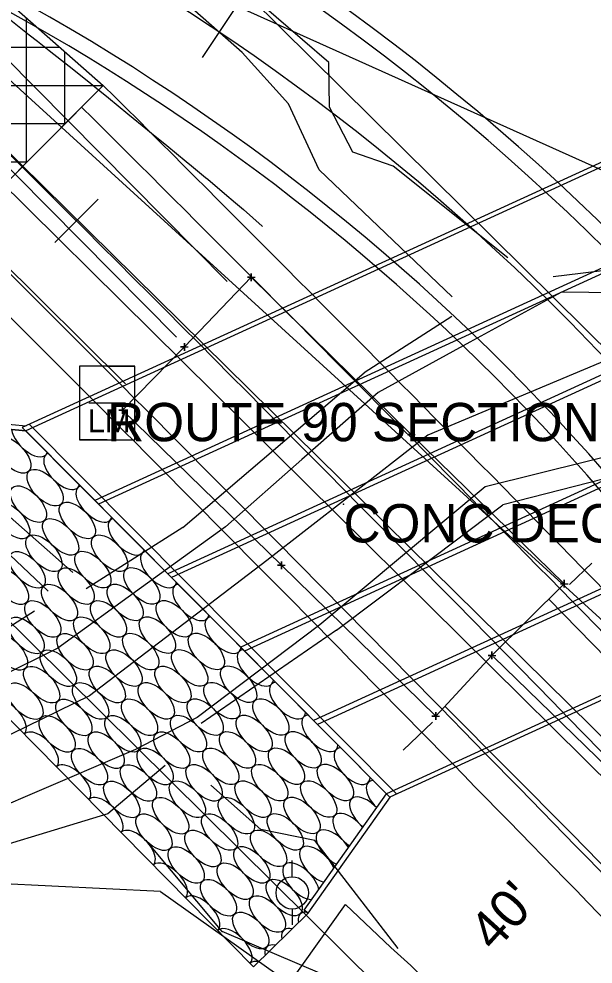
# Model space of a CAD drawing. Extents: x 1660112 to 1662239, y 668919 to 671377.
# Drawn here: x 1661235.6 to 1661310.6, y 670188.6 to 670311.9 of the extents above; entities that cross this region are included whole.
import ezdxf

# ---------------------------------------------------------------- set-up
doc = ezdxf.new("R2010")
doc.units = 0
for name, color, linetype in [('R_Axis', 7, 'Continuous'), ('R_Concrete', 7, 'Continuous'), ('R_Concrete Hidden', 7, 'Continuous'), ('R_Horz Alg', 7, 'Continuous'), ('R_Horz Alg Annot', 7, 'Continuous'), ('R_Proposed Const Limits_Cut', 7, 'Continuous'), ('R_Proposed Const Limits_Fill', 7, 'Continuous'), ('R_Proposed Const Limits_Hand', 7, 'Continuous'), ('R_Proposed Road_Lane', 7, 'Continuous'), ('R_Proposed Road_Shoulder', 7, 'Continuous'), ('R_Water Annot', 7, 'Continuous'), ('S_BASELINE', 7, 'Continuous'), ('S_BRIDGE', 7, 'Continuous'), ('S_DITCHLINE', 7, 'Continuous'), ('S_EDGE_PAVEMENT', 7, 'Continuous'), ('S_EXIST_ROW', 7, 'Continuous'), ('S_EXIST_ROW_ANNOT', 7, 'Continuous'), ('S_EXISTING_ALIGNMENT', 7, 'Continuous'), ('S_LOG_MILE', 7, 'Continuous'), ('S_LOG_MILE_ANNOT', 7, 'Continuous'), ('S_MSC_PT_SYM', 7, 'Continuous'), ('S_PAVEMENT_CROWN', 7, 'Continuous'), ('S_STR_PT_SYM', 7, 'Continuous'), ('S_STREAM', 7, 'Continuous'), ('S_SURVEY_TEXT_ANNOT', 7, 'Continuous'), ('S_UTILITY_POLE', 7, 'Continuous'), ('S_UTL_PT_SYM', 7, 'Continuous'), ('S_WALL', 7, 'Continuous'), ('S_WATER_UTILITIES', 7, 'Continuous')]:
    doc.layers.add(name, color=color, linetype=linetype)

msp = doc.modelspace()

# ---------------------------------------------------------------- linework, layer by layer
at = {"layer": 'R_Axis'}
for p, q in [((1661236.63, 670293.2), (1661236.63, 670312.05)), ((1661201.2, 670308.25), (1661240.96, 670308.25)), ((1661241.63, 670298.22), (1661241.63, 670307.65)), ((1661205.82, 670303.25), (1661246.63, 670303.25)), ((1661210.44, 670298.25), (1661241.66, 670298.25)), ((1661215.06, 670293.25), (1661236.68, 670293.25))]:
    msp.add_line(p, q, dxfattribs=at)
msp.add_lwpolyline([(1661157.58, 670355.45), (1661171.41, 670369.49), (1661246.63, 670303.25), (1661225.47, 670281.99)], close=True, dxfattribs=at)
at = {"layer": 'R_Concrete'}
for p, q in [((1661313.49, 670294.08), (1661236.07, 670258.59)), ((1661313.49, 670294.08), (1661236.07, 670258.59)), ((1661208.1, 670261.48), (1661236.56, 670258.81)), ((1661208.1, 670261.48), (1661236.56, 670258.81)), ((1661208.04, 670260.82), (1661236.51, 670258.15)), ((1661208.04, 670260.82), (1661236.51, 670258.15)), ((1661236.99, 670259.01), (1661284.96, 670210.78)), ((1661236.99, 670259.01), (1661284.96, 670210.78)), ((1661236.07, 670258.59), (1661284.05, 670210.36)), ((1661236.07, 670258.59), (1661284.05, 670210.36)), ((1661361.21, 670245.74), (1661284.05, 670210.36)), ((1661361.21, 670245.74), (1661284.05, 670210.36)), ((1661272.84, 670195.64), (1661283.61, 670210.8)), ((1661272.84, 670195.64), (1661283.61, 670210.8)), ((1661273.39, 670195.25), (1661284.14, 670210.41)), ((1661273.39, 670195.25), (1661284.14, 670210.41)), ((1661272.84, 670195.64), (1661273.39, 670195.25)), ((1661272.84, 670195.64), (1661273.39, 670195.25))]:
    msp.add_line(p, q, dxfattribs=at)
at = {"layer": 'R_Concrete Hidden'}
for p, q in [((1661313.92, 670293.64), (1661236.51, 670258.15)), ((1661313.92, 670293.64), (1661236.51, 670258.15)), ((1661322.89, 670284.55), (1661245.53, 670249.08)), ((1661322.89, 670284.55), (1661245.53, 670249.08)), ((1661323.39, 670284.05), (1661246.03, 670248.58)), ((1661323.39, 670284.05), (1661246.03, 670248.58)), ((1661332.36, 670274.96), (1661255.05, 670239.51)), ((1661332.36, 670274.96), (1661255.05, 670239.51)), ((1661332.86, 670274.46), (1661255.55, 670239.01)), ((1661332.86, 670274.46), (1661255.55, 670239.01)), ((1661341.83, 670265.37), (1661264.57, 670229.94)), ((1661341.83, 670265.37), (1661264.57, 670229.94)), ((1661342.33, 670264.87), (1661265.07, 670229.44)), ((1661342.33, 670264.87), (1661265.07, 670229.44)), ((1661351.3, 670255.78), (1661274.09, 670220.37)), ((1661351.3, 670255.78), (1661274.09, 670220.37)), ((1661351.8, 670255.27), (1661274.59, 670219.87)), ((1661351.8, 670255.27), (1661274.59, 670219.87)), ((1661360.78, 670246.19), (1661283.61, 670210.8)), ((1661360.78, 670246.19), (1661283.61, 670210.8))]:
    msp.add_line(p, q, dxfattribs=at)
at = {"layer": 'R_Horz Alg'}
for centre, radius, start, end in [((1661098.46, 670065.94), 293.82, 23.4717, 65.7806), ((1655846.99, 664877.91), 7639.44, 42.561815, 45.430038)]:
    msp.add_arc(centre, radius, start, end, dxfattribs=at)
at = {"layer": 'R_Horz Alg Annot'}
for p, q in [((1661218.99, 670333.9), (1661322.68, 670287.26)), ((1661208.2, 670320.2), (1661344.44, 670185.98))]:
    msp.add_line(p, q, dxfattribs=at)
for points in [[(1661263.98, 670313.53), (1661259.53, 670306.88)], [(1661245.96, 670288.39), (1661240.31, 670282.73)]]:
    msp.add_lwpolyline(points, dxfattribs=at)
at = {"layer": 'R_Proposed Const Limits_Cut'}
for p, q in [((1661254.1, 670198.04), (1661158.47, 670202.77)), ((1661254.1, 670198.04), (1661270.96, 670186.08)), ((1661270.96, 670186.08), (1661278.26, 670196.37))]:
    msp.add_line(p, q, dxfattribs=at)
at = {"layer": 'R_Proposed Const Limits_Fill'}
msp.add_lwpolyline([(1661278.26, 670196.37), (1661284.16, 670190.75), (1661286.76, 670188.4), (1661293.84, 670181.4), (1661297.09, 670178.04), (1661304.19, 670170.65), (1661392.33, 670117.02)], dxfattribs=at)
at = {"layer": 'R_Proposed Const Limits_Hand'}
msp.add_lwpolyline([(1661234.35, 670311.91), (1661236.98, 670309.86), (1661238.04, 670309.03), (1661239.59, 670307.81), (1661242.18, 670305.76), (1661244.76, 670303.69), (1661245.55, 670303.05), (1661247.32, 670301.61), (1661249.86, 670299.53), (1661252.4, 670297.46), (1661252.94, 670297.02), (1661254.93, 670295.39), (1661257.46, 670293.32), (1661258.15, 670292.74), (1661259.97, 670291.24), (1661260.26, 670290.99), (1661262.46, 670289.15), (1661263.91, 670287.93), (1661264.94, 670287.04), (1661267.36, 670284.86), (1661267.41, 670284.82)], dxfattribs=at)
at = {"layer": 'R_Proposed Road_Lane'}
msp.add_line((1661228.29, 670284.82), (1661243.81, 670300.41), dxfattribs=at)
for centre, radius, start, end in [((1661098.46, 670065.94), 303.82, 23.4717, 65.7806), ((1661098.46, 670065.94), 283.82, 24.6629, 65.2815), ((1655846.99, 664877.91), 7650.44, 44.123518, 45.136018), ((1655846.99, 664877.91), 7628.44, 44.123518, 45.136018)]:
    msp.add_arc(centre, radius, start, end, dxfattribs=at)
at = {"layer": 'R_Proposed Road_Shoulder'}
msp.add_line((1661243.81, 670300.41), (1661246.63, 670303.25), dxfattribs=at)
for centre, radius, start, end in [((1661098.46, 670065.94), 305.82, 23.4717, 65.7806), ((1661098.46, 670065.94), 281.82, 25.8293, 64.1706), ((1655846.99, 664877.91), 7654.44, 44.123518, 45.136018), ((1655846.99, 664877.91), 7624.44, 44.123518, 45.136018)]:
    msp.add_arc(centre, radius, start, end, dxfattribs=at)
at = {"layer": 'R_Water Annot'}
msp.add_lwpolyline([(1661208.1, 670261.48), (1661201.05, 670254.4), (1661266.25, 670188.25), (1661273.39, 670195.25), (1661272.84, 670195.64), (1661283.61, 670210.8), (1661236.51, 670258.15), (1661208.04, 670260.82)], close=True, dxfattribs=at)
for centre in [(1661234.83, 670255.03), (1661239.04, 670250.75), (1661236.86, 670248.61), (1661234.68, 670246.46), (1661243.25, 670246.48), (1661241.07, 670244.33), (1661238.89, 670242.19), (1661247.46, 670242.2), (1661236.71, 670240.04), (1661245.28, 670240.06), (1661234.53, 670237.89), (1661243.1, 670237.91), (1661251.67, 670237.93), (1661240.92, 670235.76), (1661249.49, 670235.78), (1661238.74, 670233.62), (1661247.31, 670233.63), (1661255.88, 670233.65), (1661245.13, 670231.49), (1661253.7, 670231.51), (1661236.56, 670231.47), (1661234.38, 670229.32), (1661242.95, 670229.34), (1661251.52, 670229.36), (1661260.09, 670229.38), (1661240.77, 670227.19), (1661249.34, 670227.21), (1661257.91, 670227.23), (1661238.59, 670225.05), (1661247.16, 670225.07), (1661255.73, 670225.08), (1661264.3, 670225.1), (1661236.41, 670222.9), (1661244.98, 670222.92), (1661253.55, 670222.94), (1661262.12, 670222.96), (1661242.8, 670220.77), (1661251.37, 670220.79), (1661259.94, 670220.81), (1661268.51, 670220.83), (1661240.62, 670218.62), (1661249.19, 670218.64), (1661257.76, 670218.66), (1661266.33, 670218.68), (1661247.01, 670216.5), (1661255.58, 670216.51), (1661264.15, 670216.53), (1661272.72, 670216.55), (1661244.83, 670214.35), (1661253.4, 670214.37), (1661261.97, 670214.39), (1661270.54, 670214.41), (1661251.22, 670212.22), (1661259.79, 670212.24), (1661268.36, 670212.26), (1661276.93, 670212.28), (1661249.04, 670210.07), (1661257.61, 670210.09), (1661266.18, 670210.11), (1661274.75, 670210.13), (1661255.43, 670207.95), (1661264, 670207.96), (1661272.57, 670207.98), (1661253.25, 670205.8), (1661261.82, 670205.82), (1661270.39, 670205.84), (1661259.64, 670203.67), (1661268.21, 670203.69), (1661257.46, 670201.52), (1661266.03, 670201.54), (1661263.85, 670199.4), (1661261.67, 670197.25), (1661270.24, 670197.27), (1661268.06, 670195.12), (1661265.88, 670192.97)]:
    msp.add_ellipse(centre, major_axis=(-2.1, 2.14), ratio=0.51, dxfattribs=at)
for centre, start_param, end_param in [((1661237.01, 670257.18), 0.607063, 3.367089), ((1661241.22, 670252.9), 6.057174, 9.670713), ((1661245.43, 670248.63), 6.036635, 9.691253), ((1661249.64, 670244.35), 6.015984, 9.711904), ((1661253.85, 670240.08), 5.995211, 9.732677), ((1661258.06, 670235.8), 5.974304, 9.753584), ((1661262.27, 670231.52), 5.953252, 9.774635), ((1661266.48, 670227.25), 5.932043, 9.795845), ((1661270.69, 670222.97), 5.910662, 9.817226), ((1661234.23, 670220.75), 3.13375, 6.292995), ((1661274.9, 670218.7), 5.889095, 9.838793), ((1661238.44, 670216.48), 3.135712, 6.291032), ((1661279.11, 670214.42), 5.867328, 9.86056), ((1661242.65, 670212.2), 3.137675, 6.28907), ((1661283.32, 670210.15), 5.845343, 7.895496), ((1661246.86, 670207.93), 3.139637, 6.287107), ((1661281.14, 670208), 4.670719, 8.076405), ((1661278.96, 670205.85), 4.485289, 8.261835), ((1661251.07, 670203.65), 3.1416, 6.285145), ((1661276.78, 670203.71), 4.287602, 8.459522), ((1661274.6, 670201.56), 4.064259, 8.682865), ((1661255.28, 670199.38), 3.143562, 6.283183), ((1661272.42, 670199.41), 3.779733, 8.967391), ((1661259.49, 670195.1), 3.145524, 6.28122), ((1661274.45, 670192.99), 0.187309, 0.665811), ((1661274.45, 670192.99), 5.739423, 6.470494), ((1661263.7, 670190.83), 3.147487, 6.279258), ((1661272.27, 670190.84), 0.427968, 0.661796), ((1661272.27, 670190.84), 5.618913, 6.711153), ((1661270.09, 670188.7), 5.622949, 6.855891), ((1661270.09, 670188.7), 0.572706, 0.657759), ((1661267.91, 670186.55), 5.627007, 6.277295)]:
    msp.add_ellipse(centre, major_axis=(-2.1, 2.14), ratio=0.51, start_param=start_param, end_param=end_param, dxfattribs=at)
at = {"layer": 'S_BASELINE'}
msp.add_line((1660813.76, 670687.35), (1661335.19, 670212.07), dxfattribs=at)
at = {"layer": 'S_BRIDGE'}
for p, q in [((1661257.22, 670269.12), (1661265.95, 670278.2)), ((1661265.95, 670278.2), (1661286.82, 670257.7)), ((1661249.15, 670260.87), (1661257.22, 670269.12)), ((1661269.88, 670240.62), (1661249.15, 670260.87)), ((1661286.82, 670257.7), (1661306.8, 670238.22)), ((1661290.03, 670220.95), (1661269.88, 670240.62)), ((1661306.8, 670238.22), (1661297.35, 670228.87)), ((1661297.35, 670228.87), (1661290.03, 670220.95))]:
    msp.add_line(p, q, dxfattribs=at)
at = {"layer": 'S_DITCHLINE'}
for points in [[(1661242.65, 670239.7), (1661224.03, 670256.09), (1661205.42, 670272.49), (1661195.13, 670280.52), (1661184.84, 670288.55), (1661175.36, 670299.38), (1661165.88, 670310.21), (1661156.4, 670321.03), (1661146.92, 670331.86), (1661137.55, 670341.19), (1661128.17, 670350.53), (1661118.79, 670359.86), (1661109.42, 670369.2), (1661097.31, 670380.98), (1661085.2, 670392.76), (1661068.34, 670408.15), (1661052.11, 670423.79), (1661035.88, 670439.43), (1661020.34, 670449.45), (1661008.68, 670464.67), (1660997.02, 670479.89), (1660983.41, 670495.38), (1660969.79, 670510.86)], [(1661239.43, 670237.24), (1661221.97, 670253.79), (1661204.51, 670270.33), (1661193.84, 670278.71), (1661183.17, 670287.08), (1661172.33, 670296.55), (1661161.49, 670306.02), (1661150.65, 670315.49), (1661139.81, 670324.96), (1661131.17, 670334.51), (1661122.52, 670344.05), (1661113.88, 670353.6), (1661105.24, 670363.14), (1661089.73, 670379.71), (1661086.66, 670381), (1661070.62, 670396.48), (1661054.58, 670411.96), (1661038.54, 670427.44), (1661022.5, 670442.92), (1661007.06, 670459.45), (1660991.62, 670475.99), (1660978.8, 670491.92), (1660965.98, 670507.85)], [(1661299.45, 670280.74), (1661284.47, 670292.7), (1661279.2, 670294.55), (1661276.17, 670300.4), (1661276.07, 670306.25), (1661258.9, 670321.05), (1661241.72, 670335.84), (1661231.17, 670346.95), (1661220.61, 670358.06), (1661210.06, 670369.17), (1661199.5, 670380.28), (1661190.45, 670390.39), (1661181.41, 670400.5), (1661172.36, 670410.61), (1661163.31, 670420.71), (1661149.32, 670433.4), (1661135.33, 670446.1), (1661121.34, 670458.79), (1661107.35, 670471.48)], [(1661292.16, 670275.66), (1661274.83, 670292.21), (1661270.79, 670300.84), (1661264.75, 670307.54), (1661250.97, 670319.7), (1661237.18, 670331.85), (1661227.07, 670342.64), (1661216.95, 670353.42), (1661206.84, 670364.21), (1661196.72, 670375), (1661186.88, 670384.5), (1661177.03, 670394.01), (1661167.19, 670403.51), (1661157.34, 670413.01), (1661144.39, 670427.16), (1661131.45, 670441.31), (1661118.5, 670455.46), (1661105.55, 670469.61)], [(1661285.14, 670190.64), (1661274.25, 670204.7), (1661267.2, 670206.15), (1661260.68, 670211.95)]]:
    msp.add_lwpolyline(points, dxfattribs=at)
at = {"layer": 'S_EDGE_PAVEMENT'}
for points in [[(1661249.53, 670264.29), (1661232.81, 670280.83), (1661216.09, 670297.37), (1661206.48, 670306.91), (1661196.87, 670316.45), (1661187.26, 670325.99), (1661177.65, 670335.53), (1661168.35, 670344.75), (1661159.06, 670353.98), (1661149.76, 670363.2), (1661140.47, 670372.43), (1661130.68, 670382.11), (1661120.89, 670391.8), (1661111.1, 670401.49), (1661101.31, 670411.17), (1661084.98, 670427.32), (1661068.65, 670443.47), (1661052.78, 670459.1), (1661036.91, 670474.73), (1661025.66, 670485.67), (1661014.42, 670496.6), (1661003.17, 670507.54), (1660991.93, 670518.47), (1660974.69, 670535.16)], [(1661262.8, 670277.66), (1661246.17, 670294.45), (1661229.53, 670311.23), (1661220, 670320.86), (1661210.47, 670330.49), (1661200.95, 670340.13), (1661191.42, 670349.76), (1661181.92, 670359.12), (1661172.42, 670368.49), (1661162.93, 670377.85), (1661153.43, 670387.22), (1661143.78, 670396.82), (1661134.14, 670406.42), (1661124.5, 670416.02), (1661114.85, 670425.63), (1661098.32, 670441.78), (1661081.78, 670457.93), (1661066.15, 670473.94), (1661050.52, 670489.95), (1661039.51, 670500.52), (1661028.5, 670511.09), (1661017.49, 670521.66), (1661006.48, 670532.23)], [(1661528.89, 670006.64), (1661525.81, 670010.93), (1661521.19, 670007.06), (1661512.12, 670017.42), (1661503.06, 670027.78), (1661494.14, 670038.45), (1661485.22, 670049.12), (1661475.65, 670058.13), (1661469.7, 670064.69), (1661453.26, 670082.63), (1661441.58, 670095.54), (1661429.9, 670108.45), (1661415.33, 670123.89), (1661400.76, 670139.32), (1661387.62, 670152.61), (1661374.47, 670165.9), (1661358.81, 670181.9), (1661343.14, 670197.9), (1661339.48, 670201.44), (1661329.75, 670211.05), (1661320.02, 670220.65), (1661304.77, 670236.19)], [(1661507.57, 669985.17), (1661503.63, 669990.55), (1661503.83, 669996.41), (1661492.59, 670008.33), (1661484.98, 670015.56), (1661475.91, 670025.37), (1661466.84, 670035.18), (1661454.4, 670049.73), (1661445.95, 670059), (1661437.51, 670068.28), (1661425.39, 670081.13), (1661413.28, 670093.99), (1661399.68, 670108.94), (1661386.08, 670123.89), (1661373.13, 670137.66), (1661360.18, 670151.43), (1661345.14, 670167.24), (1661330.11, 670183.04), (1661325.69, 670187.24), (1661316.74, 670196.41), (1661307.8, 670205.57), (1661291.28, 670222.16)]]:
    msp.add_lwpolyline(points, dxfattribs=at)
at = {"layer": 'S_EXIST_ROW'}
for p, q in [((1661404.92, 670177.11), (1660401.45, 671169.67)), ((1661347.41, 670121.48), (1660345.19, 671112.79))]:
    msp.add_line(p, q, dxfattribs=at)
at = {"layer": 'S_EXISTING_ALIGNMENT'}
msp.add_line((1661376.17, 670149.3), (1660373.32, 671141.23), dxfattribs=at)
at = {"layer": 'S_LOG_MILE'}
for p, q in [((1661247.15, 670266.61), (1661250.75, 670266.61)), ((1661244.75, 670261.81), (1661249.55, 670261.81)), ((1661247.15, 670257.01), (1661243.55, 670257.01))]:
    msp.add_line(p, q, dxfattribs=at)
msp.add_lwpolyline([(1661250.75, 670266.61), (1661243.55, 670266.61), (1661243.55, 670257.01), (1661250.75, 670257.01)], close=True, dxfattribs=at)
at = {"layer": 'S_MSC_PT_SYM'}
msp.add_lwpolyline([(1661277.99, 670248.61), (1661277.99, 670248.66), (1661277.99, 670248.61), (1661277.94, 670248.61), (1661277.99, 670248.61), (1661277.99, 670248.56), (1661277.99, 670248.61), (1661278.04, 670248.61)], dxfattribs=at)
at = {"layer": 'S_PAVEMENT_CROWN'}
for points in [[(1661256.17, 670270.41), (1661239.48, 670287.26), (1661222.79, 670304.1), (1661213.05, 670313.75), (1661203.32, 670323.4), (1661193.59, 670333.05), (1661183.85, 670342.7), (1661174.57, 670351.81), (1661165.29, 670360.92), (1661156.01, 670370.03), (1661146.73, 670379.14), (1661137.08, 670388.79), (1661127.43, 670398.43), (1661117.78, 670408.07), (1661108.13, 670417.71), (1661091.69, 670433.83), (1661075.25, 670449.95), (1661059.39, 670465.57), (1661043.53, 670481.18), (1661032.32, 670491.86), (1661021.11, 670502.53), (1661009.9, 670513.21), (1660998.68, 670523.89), (1660981.9, 670540.69)], [(1661518.06, 669996.03), (1661505.4, 670009.31), (1661492.74, 670022.59), (1661480.19, 670036.99), (1661467.64, 670051.39), (1661473.76, 670044.39), (1661461.34, 670057.98), (1661445.4, 670075.38), (1661443.99, 670076.39), (1661432.69, 670088.65), (1661421.39, 670100.9), (1661407.48, 670115.88), (1661393.57, 670130.85), (1661380.41, 670144.59), (1661367.25, 670158.33), (1661351.88, 670174.26), (1661336.51, 670190.18), (1661332.38, 670194.36), (1661323.21, 670203.51), (1661314.05, 670212.66), (1661297.56, 670228.68)]]:
    msp.add_lwpolyline(points, dxfattribs=at)
at = {"layer": 'S_STR_PT_SYM'}
for points in [[(1661265.95, 670278.2), (1661265.95, 670278.7), (1661265.95, 670278.2), (1661265.45, 670278.2), (1661265.95, 670278.2), (1661265.95, 670277.7), (1661265.95, 670278.2), (1661266.45, 670278.2)], [(1661257.22, 670269.12), (1661257.22, 670269.62), (1661257.22, 670269.12), (1661256.72, 670269.12), (1661257.22, 670269.12), (1661257.22, 670268.62), (1661257.22, 670269.12), (1661257.72, 670269.12)], [(1661249.15, 670260.87), (1661249.15, 670261.37), (1661249.15, 670260.87), (1661248.65, 670260.87), (1661249.15, 670260.87), (1661249.15, 670260.37), (1661249.15, 670260.87), (1661249.65, 670260.87)], [(1661286.82, 670257.7), (1661286.82, 670258.2), (1661286.82, 670257.7), (1661286.32, 670257.7), (1661286.82, 670257.7), (1661286.82, 670257.2), (1661286.82, 670257.7), (1661287.32, 670257.7)], [(1661269.88, 670240.62), (1661269.88, 670241.12), (1661269.88, 670240.62), (1661269.38, 670240.62), (1661269.88, 670240.62), (1661269.88, 670240.12), (1661269.88, 670240.62), (1661270.38, 670240.62)], [(1661306.8, 670238.22), (1661306.8, 670238.72), (1661306.8, 670238.22), (1661306.3, 670238.22), (1661306.8, 670238.22), (1661306.8, 670237.72), (1661306.8, 670238.22), (1661307.3, 670238.22)], [(1661297.35, 670228.87), (1661297.35, 670229.37), (1661297.35, 670228.87), (1661296.85, 670228.87), (1661297.35, 670228.87), (1661297.35, 670228.37), (1661297.35, 670228.87), (1661297.85, 670228.87)], [(1661290.03, 670220.95), (1661290.03, 670221.45), (1661290.03, 670220.95), (1661289.53, 670220.95), (1661290.03, 670220.95), (1661290.03, 670220.45), (1661290.03, 670220.95), (1661290.53, 670220.95)]]:
    msp.add_lwpolyline(points, dxfattribs=at)
at = {"layer": 'S_STREAM'}
for points in [[(1661620.34, 670335.21), (1661597.17, 670329.75), (1661574, 670324.29), (1661550.82, 670318.83), (1661527.65, 670313.37), (1661513.53, 670311.73), (1661499.41, 670310.09), (1661492.64, 670311.04), (1661490.16, 670306.19), (1661483.49, 670303.19), (1661469.16, 670295.94), (1661446.28, 670293.35), (1661423.4, 670290.75), (1661409.17, 670289.53), (1661394.93, 670288.3), (1661370.48, 670288.49), (1661352.9, 670285.18), (1661335.31, 670281.88), (1661320.32, 670280.07), (1661305.33, 670278.26)], [(1661623.56, 670311.06), (1661600.76, 670306.67), (1661577.96, 670302.29), (1661555.16, 670297.9), (1661532.36, 670293.52), (1661508.21, 670288.49), (1661492.78, 670284.3), (1661477.36, 670280.12), (1661459.42, 670277.44), (1661441.48, 670274.76), (1661423.55, 670272.09), (1661405.61, 670269.41), (1661388.57, 670266.5), (1661371.54, 670263.59), (1661354.51, 670260.67), (1661337.47, 670257.76), (1661319.37, 670253.79), (1661298.79, 670248.53)], [(1661384.22, 670282.64), (1661367.85, 670280.4), (1661351.48, 670278.17), (1661335.11, 670275.93), (1661320.77, 670276.1), (1661306.42, 670276.27), (1661294.47, 670269.73), (1661282.53, 670263.19), (1661272.56, 670254.42), (1661262.59, 670245.66), (1661251.64, 670237.74), (1661240.7, 670229.82), (1661218.36, 670218.7), (1661205.19, 670219.73), (1661192.01, 670220.76), (1661178.84, 670221.78), (1661165.66, 670222.81), (1661153.9, 670226.65)], [(1661386.08, 670275.8), (1661370.4, 670273.52), (1661354.73, 670271.25), (1661339.06, 670268.97), (1661325.94, 670268.28), (1661312.82, 670267.6), (1661300.92, 670262.59), (1661289.01, 670257.59), (1661278.51, 670249.41), (1661268, 670241.23), (1661256.41, 670232.4), (1661244.82, 670223.57), (1661232.52, 670217.57), (1661220.23, 670211.57), (1661206.02, 670213.11), (1661191.8, 670214.64), (1661177.59, 670216.17), (1661163.37, 670217.71), (1661152.07, 670221.36)], [(1661292.14, 670273.1), (1661280.7, 670265.75)], [(1661387.42, 670269.33), (1661371.06, 670266.44), (1661354.71, 670263.56), (1661338.35, 670260.67), (1661316.6, 670255.88), (1661296.46, 670250.86), (1661285.68, 670241.86), (1661274.9, 670232.86), (1661258.9, 670220.78), (1661250.84, 670216.6), (1661237.04, 670210.68), (1661223.24, 670204.75), (1661207.85, 670205.5), (1661192.45, 670206.25), (1661177.06, 670207), (1661161.67, 670207.75), (1661149.8, 670215.11)], [(1661257.02, 670245.54), (1661268.86, 670255.65), (1661280.7, 670265.75)], [(1661277.08, 670232.16), (1661287.93, 670240.35), (1661298.79, 670248.53)], [(1661257.02, 670245.54), (1661244.41, 670237.57)], [(1661237.64, 670234.64), (1661226.98, 670227.9), (1661216.31, 670221.16), (1661203.67, 670222.32), (1661191.03, 670223.48), (1661178.4, 670224.64), (1661165.76, 670225.81), (1661154.74, 670229.38), (1661141.63, 670233.02), (1661128.51, 670236.67), (1661114.77, 670235.78), (1661104.13, 670231.11)], [(1661277.08, 670232.16), (1661259.42, 670219.97)], [(1661254.7, 670214.48), (1661247.25, 670208.21), (1661225.75, 670201.67), (1661211.58, 670201.81), (1661197.41, 670201.96), (1661183.24, 670202.1), (1661169.07, 670202.24), (1661154.61, 670206.46), (1661140.15, 670210.67), (1661126.98, 670218.08), (1661113.36, 670211.62), (1661104.67, 670201.88), (1661095.98, 670192.14), (1661082.19, 670186.21), (1661068.4, 670180.28), (1661054.61, 670174.34), (1661040.82, 670168.41), (1661022.25, 670157.95), (1661011.73, 670139.15), (1661001.22, 670120.35)]]:
    msp.add_lwpolyline(points, dxfattribs=at)
at = {"layer": 'S_UTILITY_POLE'}
for p, q in [((1661271.27, 670199.96), (1661271.27, 670202.09)), ((1661271.27, 670195.74), (1661271.27, 670193.69))]:
    msp.add_line(p, q, dxfattribs=at)
msp.add_circle((1661271.29, 670197.88), 2.11, dxfattribs=at)
at = {"layer": 'S_UTL_PT_SYM'}
for points in [[(1661252.22, 670204.72), (1661252.22, 670204.77), (1661252.22, 670204.72), (1661252.17, 670204.72), (1661252.22, 670204.72), (1661252.22, 670204.67), (1661252.22, 670204.72), (1661252.27, 670204.72)], [(1661262.17, 670192.84), (1661262.17, 670192.89), (1661262.17, 670192.84), (1661262.12, 670192.84), (1661262.17, 670192.84), (1661262.17, 670192.79), (1661262.17, 670192.84), (1661262.22, 670192.84)]]:
    msp.add_lwpolyline(points, dxfattribs=at)
at = {"layer": 'S_WALL'}
for points in [[(1661310.4, 670240.92), (1661307.47, 670238.13)], [(1661285.79, 670216.52), (1661289.62, 670220.15)]]:
    msp.add_lwpolyline(points, dxfattribs=at)
at = {"layer": 'S_WATER_UTILITIES'}
for p, q in [((1661262.17, 670192.84), (1661252.22, 670204.72)), ((1661279.71, 670185.37), (1661262.17, 670192.84))]:
    msp.add_line(p, q, dxfattribs=at)

# ---------------------------------------------------------------- texts
at = {"layer": 'S_EXIST_ROW_ANNOT'}
msp.add_text("40'", height=5, rotation=47.7397, dxfattribs=at).set_placement((1661297.68, 670190.03))
at = {"layer": 'S_LOG_MILE'}
msp.add_text('LM', height=3, rotation=360, dxfattribs=at).set_placement((1661244.61, 670257.97))
at = {"layer": 'S_LOG_MILE_ANNOT'}
msp.add_text('ROUTE 90 SECTION 5 LOG MILE 0.', height=5, dxfattribs=at).set_placement((1661247.15, 670256.81))
at = {"layer": 'S_SURVEY_TEXT_ANNOT'}
msp.add_text('CONC DECK WOOD PIERS AND BEAMS', height=5, dxfattribs=at).set_placement((1661277.99, 670243.61))

doc.saveas('drawing.dxf')
